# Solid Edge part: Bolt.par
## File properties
Author: Deepak Maini
Template: Normal.par
Last saved by: CADCIM
Revision: 3
Application: Solid Edge
Accuracy: 0.99
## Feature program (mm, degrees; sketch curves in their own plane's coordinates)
sketch for "unnamed Protrusion 1" plane through (0, 0, 0) normal (0, 0, 1) x-axis (1, 0, 0)
  line (-12, 12) -> (-12, -12)
  line (-12, -12) -> (12, -12)
  line (12, -12) -> (12, 12)
  line (12, 12) -> (-12, 12)
extrude "unnamed Protrusion 1" add finite 8 along +normal
sketch for "ExtrudedProtrusion_2" plane through (0, 0, 0) normal (0, 0, 1) x-axis (1, 0, 0)
  circle centre (0, 0) radius 6
extrude "ExtrudedProtrusion_2" add finite 104 along +normal
sketch for "unnamed RevolvedCutout 1" plane through (-12, 12, 4) normal (-0.707107, -0.707107, 0) x-axis (0, 0, -1)
  arc centre (-3, 7) radius 7 from (-3, 0) to (4, 7) ccw
  line (4, 7) -> (4, 0)
  line (-3, 0) -> (4, 0)
revolve "unnamed RevolvedCutout 1" cut full turn 360 deg about sketch line (9.5376, 16.9706) -> (-8.8435, 16.9706)
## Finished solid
Body 1: solid body, 9 faces, 15 edges, 8 vertices.
  Faces by surface: plane 7, cylinder 1, torus 1
  Edges by curve: line 8, intersection 4, circle 3
Bounding box of the edges (mm; curved faces can reach further): 24.000 x 24.000 x 104.000, from (-12, -12, 0) to (12, 12, 104).
Cylindrical faces by radius (mm): R6 x1
Toroidal faces (ring radius, tube radius in mm): R9.9706 r7 x1
Planar faces by outward normal: +x 1, +y 1, +z 2, -x 1, -y 1, -z 1
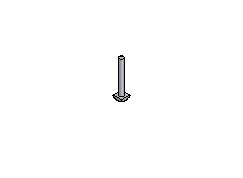
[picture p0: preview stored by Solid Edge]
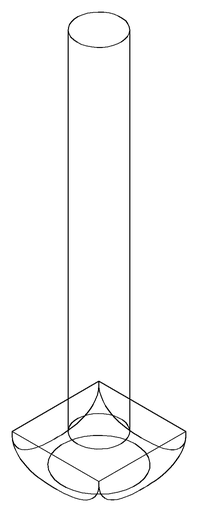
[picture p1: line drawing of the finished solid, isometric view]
